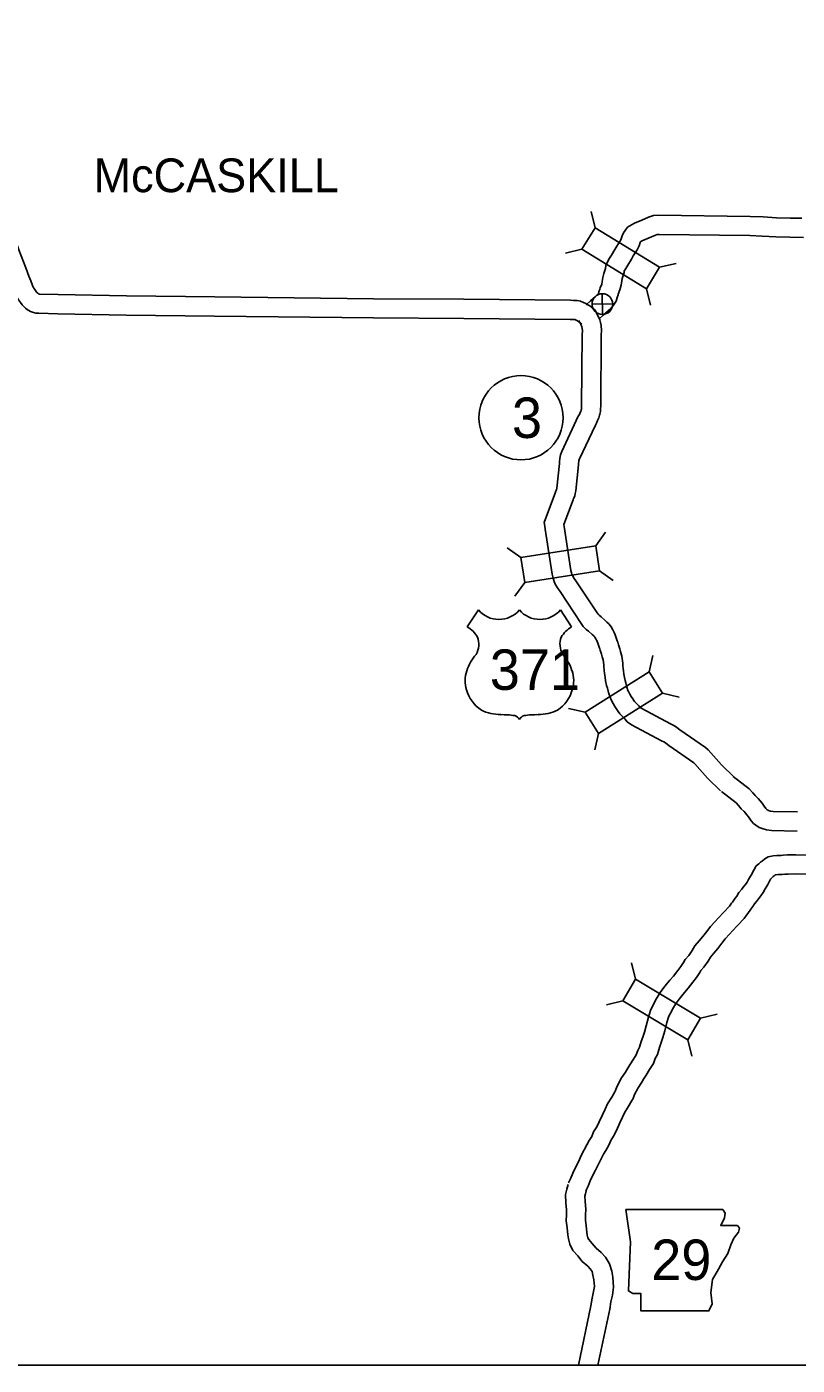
# Model space of a CAD drawing. Extents: x 79818 to 83933, y 50884 to 53307.
# Drawn here: x 81014.4 to 81175.4, y 52610.7 to 52890.4 of the extents above; entities that cross this region are included whole.
import ezdxf

# ---------------------------------------------------------------- set-up
doc = ezdxf.new("R2010")
doc.units = 0
for name, color, linetype in [('Level 10', 7, 'Continuous'), ('Level 15', 7, 'Continuous'), ('Level 20', 7, 'Continuous'), ('Level 21', 7, 'Continuous'), ('Level 22', 7, 'Continuous'), ('Level 26', 7, 'Continuous'), ('Level 27', 7, 'Continuous'), ('Level 6', 7, 'Continuous'), ('R_No Plot', 7, 'Continuous')]:
    doc.layers.add(name, color=color, linetype=linetype)

msp = doc.modelspace()

# ---------------------------------------------------------------- linework, layer by layer
at = {"layer": 'Level 10'}
for points in [[(81131.31, 52832.27), (81132.24, 52833.12), (81133.27, 52833.99), (81133.58, 52834.29), (81133.83, 52834.57), (81133.89, 52834.66), (81133.98, 52835), (81134.18, 52835.56), (81134.24, 52835.8), (81134.56, 52836.59), (81134.69, 52837.12), (81134.82, 52837.97), (81135, 52838.82), (81135.34, 52839.86), (81135.41, 52840.47), (81136.09, 52841.77), (81136.6, 52842.64), (81137.32, 52843.81), (81137.71, 52844.54), (81138.08, 52845.09), (81138.48, 52845.71), (81138.63, 52846.04), (81138.84, 52846.7), (81139.11, 52847.31), (81139.45, 52847.77), (81139.96, 52848.52), (81141.43, 52849.34), (81142.96, 52849.97), (81144.37, 52850.55), (81145.37, 52850.92), (81146.47, 52850.98), (81165.61, 52850.73), (81168.32, 52850.62), (81171.11, 52850.44), (81173.98, 52850.39), (81176.37, 52850.35)], [(81133.95, 52829.27), (81134.88, 52830.12), (81135.93, 52831.01), (81136.47, 52831.51), (81137.06, 52832.19), (81137.59, 52833.04), (81137.8, 52833.8), (81138, 52834.36), (81138.04, 52834.52), (81138.39, 52835.37), (81138.62, 52836.36), (81138.75, 52837.25), (81138.87, 52837.79), (81139.26, 52839), (81139.29, 52839.27), (81139.58, 52839.82), (81140.03, 52840.58), (81140.79, 52841.82), (81141.14, 52842.48), (81141.42, 52842.89), (81141.99, 52843.77), (81142.37, 52844.59), (81142.59, 52845.29), (81142.59, 52845.3), (81142.7, 52845.45), (81142.72, 52845.48), (81143.18, 52845.73), (81144.48, 52846.27), (81145.82, 52846.82), (81146.19, 52846.95), (81146.56, 52846.97), (81165.5, 52846.73), (81168.11, 52846.62), (81170.95, 52846.44), (81173.9, 52846.39), (81176.72, 52846.34)], [(81181.86, 52717.23), (81175.13, 52717.37), (81173.37, 52717.31), (81172.5, 52717.27), (81172.06, 52717.21), (81171.74, 52717.22), (81171.18, 52717.2), (81170.42, 52717.12), (81170.03, 52717.05), (81169.38, 52716.93), (81168.69, 52716.53), (81168.15, 52716.11), (81167.75, 52715.79), (81167.41, 52715.47), (81166.83, 52715.02), (81166.35, 52714.14), (81165.79, 52713.09), (81165.64, 52712.85), (81165.28, 52712.22), (81164.96, 52711.66), (81164.6, 52711.17), (81164.15, 52710.56), (81163.84, 52710.17), (81163.25, 52709.5), (81162.78, 52708.73), (81162.45, 52708.26), (81161.93, 52707.48), (81161.73, 52707.24), (81161.26, 52706.64), (81160.08, 52705.35), (81158.89, 52704.14), (81158.29, 52703.41), (81157.3, 52702.35), (81156.51, 52701.31), (81155.73, 52700.31), (81154.92, 52699.36), (81154.06, 52698.3), (81153.46, 52697.33), (81152.75, 52696.34), (81152, 52695.45), (81151.67, 52694.87), (81151.11, 52694.03), (81150.45, 52693.19), (81149.54, 52692.02), (81148.79, 52691.16), (81148.13, 52690.32), (81147.58, 52689.6), (81146.82, 52688.61), (81146.35, 52687.85), (81145.83, 52686.95), (81145.54, 52686.32), (81145.18, 52685.71), (81144.8, 52684.83), (81144.35, 52683.4), (81143.89, 52681.64), (81143.52, 52680.31), (81143.15, 52679.21), (81142.85, 52678.34), (81142.49, 52677.16), (81142.12, 52676.43), (81141.77, 52675.55), (81141.21, 52674.64), (81140.44, 52673.45), (81139.82, 52672.45), (81139.55, 52671.93), (81138.73, 52670.76), (81137.76, 52668.89), (81137.46, 52668.12), (81137.3, 52667.81), (81136.68, 52666.73), (81135.8, 52665.33), (81135.28, 52664.18), (81134.76, 52663.02), (81134.04, 52661.53), (81133.53, 52660.5), (81132.88, 52659.44), (81132.49, 52658.49), (81131.98, 52657.63), (81131.43, 52656.74), (81130.3, 52654.5), (81129.69, 52653.22), (81128.99, 52651.88), (81128.5, 52650.81), (81128.04, 52649.66), (81127.64, 52648.78)], [(81181.92, 52713.23), (81175.15, 52713.37), (81173.53, 52713.32), (81172.87, 52713.29), (81172.3, 52713.21), (81171.77, 52713.22), (81171.45, 52713.2), (81170.98, 52713.16), (81170.84, 52713.13), (81170.63, 52712.97), (81170.39, 52712.78), (81170.02, 52712.43), (81169.94, 52712.36), (81169.87, 52712.24), (81169.28, 52711.12), (81169.08, 52710.8), (81168.74, 52710.22), (81168.32, 52709.49), (81167.82, 52708.8), (81167.32, 52708.12), (81166.9, 52707.59), (81166.48, 52707.12), (81166.14, 52706.55), (81165.76, 52706), (81165.13, 52705.07), (81164.85, 52704.73), (81164.32, 52704.05), (81162.98, 52702.59), (81161.87, 52701.46), (81161.3, 52700.78), (81160.37, 52699.77), (81159.69, 52698.87), (81158.83, 52697.78), (81157.99, 52696.79), (81157.33, 52695.98), (81156.79, 52695.11), (81155.9, 52693.88), (81155.3, 52693.16), (81155.08, 52692.77), (81154.36, 52691.68), (81153.6, 52690.72), (81152.62, 52689.47), (81151.87, 52688.6), (81151.29, 52687.88), (81150.76, 52687.18), (81150.12, 52686.34), (81149.78, 52685.78), (81149.39, 52685.12), (81149.1, 52684.47), (81148.75, 52683.89), (81148.56, 52683.43), (81148.19, 52682.29), (81147.75, 52680.6), (81147.35, 52679.14), (81146.94, 52677.91), (81146.65, 52677.09), (81146.21, 52675.65), (81145.77, 52674.79), (81145.36, 52673.75), (81144.59, 52672.5), (81143.83, 52671.33), (81143.3, 52670.46), (81142.97, 52669.84), (81142.16, 52668.68), (81141.41, 52667.24), (81141.11, 52666.46), (81140.8, 52665.88), (81140.11, 52664.68), (81139.33, 52663.43), (81138.92, 52662.53), (81138.39, 52661.33), (81137.63, 52659.77), (81137.04, 52658.57), (81136.46, 52657.62), (81136.07, 52656.69), (81135.4, 52655.56), (81134.93, 52654.79), (81133.89, 52652.73), (81133.27, 52651.43), (81132.58, 52650.11), (81132.17, 52649.23), (81131.72, 52648.1), (81131.28, 52647.13)], [(81127.53, 52648.48), (81127.26, 52647.48), (81127.01, 52646.36), (81127.1, 52644.66), (81127.22, 52643.15), (81127.2, 52642.16), (81127.17, 52640.88), (81127.32, 52639.4), (81127.49, 52637.92), (81127.63, 52637.09), (81127.88, 52635.96), (81128.53, 52634.7), (81129.56, 52633.55), (81130.51, 52632.39), (81131.65, 52631.37), (81132.17, 52630.82), (81132.54, 52630.25), (81132.73, 52629.52), (81132.89, 52628.57), (81133.03, 52627.14), (81132.88, 52626.11), (81132.54, 52624.71), (81132.31, 52623.09), (81129.69, 52610.7)], [(81131.39, 52647.43), (81131.15, 52646.53), (81131.04, 52646.02), (81131.09, 52644.91), (81131.22, 52643.28), (81131.2, 52642.08), (81131.18, 52641.03), (81131.3, 52639.82), (81131.45, 52638.5), (81131.56, 52637.86), (81131.68, 52637.32), (81131.85, 52636.98), (81132.6, 52636.15), (81133.41, 52635.16), (81134.44, 52634.23), (81135.33, 52633.3), (81136.23, 52631.9), (81136.65, 52630.37), (81136.86, 52629.09), (81137.05, 52627.04), (81136.81, 52625.35), (81136.48, 52623.97), (81136.26, 52622.4), (81133.78, 52610.7)]]:
    msp.add_lwpolyline(points, dxfattribs=at)
at = {"layer": 'Level 15'}
for points in [[(81008.91, 52854.75), (81012.76, 52843.76), (81014.23, 52839.98), (81014.82, 52838.28), (81015.25, 52837.25), (81015.53, 52836.54), (81015.7, 52836.1), (81015.81, 52835.87), (81015.89, 52835.75), (81016.07, 52835.46), (81016.35, 52835.05), (81016.44, 52834.94), (81016.69, 52834.69), (81016.76, 52834.62), (81016.91, 52834.52), (81017.13, 52834.5), (81020.96, 52834.39), (81035.25, 52834.12), (81053.7, 52833.91)], [(81005.13, 52853.43), (81009.01, 52842.37), (81010.47, 52838.59), (81011.08, 52836.86), (81011.53, 52835.76), (81011.81, 52835.05), (81012.04, 52834.5), (81012.33, 52833.88), (81012.54, 52833.57), (81012.71, 52833.29), (81013.1, 52832.72), (81013.44, 52832.27), (81013.88, 52831.84), (81014.14, 52831.58), (81014.56, 52831.23), (81014.84, 52831.09), (81015.17, 52830.86), (81015.79, 52830.65), (81016.32, 52830.54), (81016.96, 52830.51), (81020.87, 52830.4), (81035.19, 52830.12), (81053.66, 52829.91)], [(81053.7, 52833.91), (81053.71, 52833.91), (81086.89, 52833.53)], [(81086.88, 52833.53), (81105.76, 52833.43), (81128.04, 52833.21), (81128.64, 52833.19), (81129.43, 52833.19), (81130.12, 52833), (81130.76, 52832.78), (81131.22, 52832.51), (81131.55, 52832.35), (81132.08, 52832.05), (81132.43, 52831.75), (81132.54, 52831.66), (81133.21, 52831.14)], [(81053.66, 52829.91), (81086.85, 52829.53)], [(81086.86, 52829.53), (81105.73, 52829.43), (81127.97, 52829.21), (81128.59, 52829.19), (81128.87, 52829.19), (81128.93, 52829.18), (81129.09, 52829.12), (81129.35, 52828.97), (81129.71, 52828.8), (81129.74, 52828.78), (81129.82, 52828.71), (81130.04, 52828.53), (81130.41, 52828.25)], [(81129.82, 52828.97), (81130.36, 52827.84), (81130.4, 52827.67), (81130.49, 52827.3), (81130.53, 52826.86), (81130.48, 52826.07), (81130.37, 52811.17), (81130.35, 52810.82), (81130.34, 52810.5), (81130.34, 52810.49), (81130.28, 52810.29), (81130.2, 52810), (81130.09, 52809.76), (81129.9, 52809.37), (81129.68, 52808.97), (81126.21, 52801.59), (81125.98, 52800.89), (81125.89, 52800.57), (81125.82, 52800.11), (81125.75, 52799.51), (81125.74, 52799.11), (81125.17, 52793.98), (81125.11, 52793.62), (81125, 52793.4), (81124.82, 52792.93), (81122.83, 52787.57), (81122.56, 52786.75), (81122.65, 52785.99), (81122.72, 52785.39), (81124.21, 52775.97), (81124.42, 52775.17), (81124.57, 52774.64), (81124.87, 52773.92), (81125.47, 52772.91), (81125.88, 52772.33), (81130.3, 52765.7), (81130.7, 52765.07), (81131.35, 52764.45), (81131.79, 52764.06), (81132.59, 52763.38), (81132.91, 52763.09), (81133.02, 52762.98), (81133.14, 52762.82), (81133.31, 52762.48), (81133.52, 52762.09)], [(81133.21, 52831.14), (81134.18, 52829.14), (81134.3, 52828.56), (81134.45, 52827.96), (81134.54, 52826.91), (81134.48, 52825.93), (81134.37, 52811.01), (81134.34, 52810.62), (81134.33, 52809.97), (81134.19, 52809.42), (81134.12, 52809.19), (81133.98, 52808.66), (81133.71, 52808.06), (81133.45, 52807.52), (81133.24, 52807.15), (81129.93, 52800.08), (81129.82, 52799.76), (81129.78, 52799.56), (81129.74, 52799.21), (81129.73, 52798.82), (81129.13, 52793.43), (81129.04, 52792.86), (81128.92, 52792.28), (81128.66, 52791.78), (81128.57, 52791.54), (81126.64, 52786.33), (81126.69, 52785.94), (81128.13, 52776.78), (81128.27, 52776.24), (81128.35, 52775.96), (81128.46, 52775.7), (81128.82, 52775.11), (81129.17, 52774.61), (81133.65, 52767.88), (81133.81, 52767.63), (81134.04, 52767.41), (81134.43, 52767.08), (81135.23, 52766.37), (81135.66, 52765.99), (81136.03, 52765.62), (81136.55, 52764.95), (81136.86, 52764.33), (81137.21, 52763.68), (81137.39, 52763.34)], [(81133.55, 52762.11), (81133.8, 52761.34), (81134.12, 52760.53), (81134.19, 52760.38), (81134.25, 52760.14), (81134.5, 52759.27), (81134.67, 52758.74), (81134.84, 52758.06), (81134.99, 52757.05), (81135.01, 52756.61), (81135.05, 52755.92), (81135.13, 52755.2), (81135.27, 52754.46), (81135.37, 52753.71), (81135.59, 52752.75), (81135.76, 52752.2), (81136, 52751.27), (81136.32, 52750.26), (81136.56, 52749.74), (81136.94, 52748.97), (81137.34, 52748.31), (81137.7, 52747.73), (81138.02, 52747.26), (81138.34, 52746.83), (81138.8, 52746.36), (81139.03, 52746.13), (81139.37, 52745.77), (81139.92, 52745.13), (81140.81, 52744.48), (81147.05, 52741.19)], [(81137.36, 52763.33), (81137.56, 52762.69), (81137.8, 52762.09), (81137.95, 52761.76), (81138.1, 52761.24), (81138.34, 52760.41), (81138.52, 52759.81), (81138.76, 52758.85), (81138.98, 52757.41), (81139, 52756.8), (81139.04, 52756.29), (81139.09, 52755.8), (81139.22, 52755.09), (81139.32, 52754.41), (81139.45, 52753.79), (81139.6, 52753.31), (81139.85, 52752.38), (81140.06, 52751.7), (81140.18, 52751.45), (81140.45, 52750.9), (81140.74, 52750.41), (81141.05, 52749.92), (81141.29, 52749.57), (81141.41, 52749.41), (81141.65, 52749.17), (81141.9, 52748.92), (81142.34, 52748.45), (81142.64, 52748.1), (81142.93, 52747.89), (81148.92, 52744.72)], [(81148.92, 52744.72), (81148.95, 52744.71), (81149.75, 52744.27), (81150.25, 52743.93), (81150.9, 52743.46), (81156.25, 52739.75), (81156.84, 52739.25), (81159.6, 52736.14), (81162.22, 52733.58)], [(81147.05, 52741.19), (81147.66, 52740.86), (81147.94, 52740.66), (81148.59, 52740.2), (81153.81, 52736.57), (81154.04, 52736.38), (81156.7, 52733.38), (81159.43, 52730.71)], [(81162.05, 52733.72), (81165.37, 52731.15), (81166.18, 52730.29), (81166.65, 52729.71), (81167.29, 52729.11), (81168.08, 52728.14), (81168.5, 52727.54), (81168.87, 52727.01), (81168.98, 52726.9), (81169.15, 52726.76), (81169.33, 52726.64), (81169.38, 52726.62), (81169.82, 52726.49), (81170.4, 52726.41), (81175.5, 52726.31)], [(81159.6, 52730.57), (81162.67, 52728.18), (81163.18, 52727.64), (81163.73, 52726.97), (81164.35, 52726.38), (81164.89, 52725.72), (81165.22, 52725.25), (81165.78, 52724.43), (81166.32, 52723.91), (81166.76, 52723.55), (81167.47, 52723.06), (81168.11, 52722.82), (81168.99, 52722.56), (81170.09, 52722.42), (81175.42, 52722.31)]]:
    msp.add_lwpolyline(points, dxfattribs=at)
at = {"layer": 'Level 20'}
for p, q in [((81133.17, 52848.37), (81132.34, 52851.79)), ((81130.41, 52843.87), (81126.99, 52843.04)), ((81146.68, 52840.1), (81150.1, 52840.93)), ((81143.92, 52835.6), (81144.75, 52832.18)), ((81133.32, 52781.92), (81135.39, 52784.76)), ((81117.67, 52779.45), (81114.82, 52781.52)), ((81134.14, 52776.7), (81136.99, 52774.63)), ((81118.49, 52774.23), (81116.42, 52771.38)), ((81144.49, 52755.58), (81145.28, 52759.01)), ((81147.3, 52751.1), (81150.73, 52750.32)), ((81131.08, 52747.15), (81127.65, 52747.93)), ((81133.89, 52742.68), (81133.1, 52739.25)), ((81141.66, 52691.36), (81140.81, 52694.78)), ((81138.95, 52686.83), (81135.54, 52685.97)), ((81155.25, 52683.22), (81158.67, 52684.08)), ((81152.54, 52678.69), (81153.4, 52675.28))]:
    msp.add_line(p, q, dxfattribs=at)
for points in [[(81146.68, 52840.1), (81133.17, 52848.37), (81130.41, 52843.87), (81143.92, 52835.6)], [(81133.32, 52781.92), (81117.67, 52779.45), (81118.49, 52774.23), (81134.14, 52776.7)], [(81133.89, 52742.68), (81147.3, 52751.1), (81144.49, 52755.58), (81131.08, 52747.15)], [(81155.25, 52683.22), (81141.66, 52691.36), (81138.95, 52686.83), (81152.54, 52678.69)]]:
    msp.add_lwpolyline(points, close=True, dxfattribs=at)
at = {"layer": 'Level 21'}
msp.add_lwpolyline([(81139.59, 52643.26), (81140.6, 52636.5), (81140.15, 52626.23), (81141.05, 52625.67), (81142.75, 52625.67), (81142.75, 52622.06), (81156.96, 52622.06), (81157.63, 52623.52), (81157.41, 52625.89), (81157.75, 52628.6), (81158.99, 52630.74), (81159.78, 52632.32), (81160.9, 52634.01), (81161.58, 52635.82), (81162.15, 52637.28), (81163.16, 52638.53), (81163.39, 52639.31), (81162.93, 52639.88), (81159.44, 52639.88), (81160.23, 52641.46), (81160.34, 52642.47), (81159.87, 52643.25)], close=True, dxfattribs=at)
at = {"layer": 'Level 22'}
for p, q in [((81108.79, 52768.53), (81106.48, 52764.96)), ((81125.95, 52768.53), (81128.25, 52764.96))]:
    msp.add_line(p, q, dxfattribs=at)
for centre, radius, start, end in [((81113.09, 52772.14), 5.62, 220.075, 319.6701), ((81121.65, 52772.14), 5.62, 220.3299, 319.925), ((81103.46, 52759.78), 6, 30.7809, 59.9883), ((81131.27, 52759.78), 6, 120.0117, 149.2191), ((81104.78, 52761.36), 4.11, 328.8105, 21.2108), ((81129.95, 52761.36), 4.11, 158.7892, 211.1895), ((81115.53, 52752.93), 9.59, 138.9565, 162.6913), ((81119.2, 52752.93), 9.59, 17.3087, 41.0435), ((81112.37, 52753.72), 6.34, 160.9576, 197.3819), ((81122.37, 52753.72), 6.34, 342.6181, 19.0424), ((81113.4, 52753.74), 7.33, 195.1074, 237.1312), ((81121.34, 52753.74), 7.33, 302.8688, 344.8926), ((81113.53, 52756.05), 9.41, 244.0771, 269.5779), ((81113.75, 52729.39), 17.24, 81.1942, 90.9539), ((81115.91, 52744.85), 1.65, 28.0342, 72.9864), ((81118.83, 52744.85), 1.65, 107.0136, 151.9658), ((81120.98, 52729.39), 17.24, 89.0461, 98.8058), ((81121.2, 52756.05), 9.41, 270.4221, 295.9229)]:
    msp.add_arc(centre, radius, start, end, dxfattribs=at)
at = {"layer": 'Level 26'}
for p, q in [((81134.76, 52830.25), (81134.66, 52834.59)), ((81132.54, 52832.37), (81136.88, 52832.47))]:
    msp.add_line(p, q, dxfattribs=at)
msp.add_circle((81134.71, 52832.42), 2.17, dxfattribs=at)
at = {"layer": 'Level 27'}
msp.add_circle((81117.7, 52808.67), 8.8, dxfattribs=at)
at = {"layer": 'R_No Plot'}
msp.add_lwpolyline([(80798.6, 53193.52), (81459.98, 53193.52), (81459.98, 52610.7), (80798.6, 52610.7)], close=True, dxfattribs=at)
msp.add_lwpolyline([(80798.6, 53193.52), (81459.98, 53193.52), (81459.98, 52610.7), (80798.6, 52610.7)], close=True, dxfattribs=at)

# ---------------------------------------------------------------- texts
at = {"layer": 'Level 21'}
msp.add_text('29', height=8.448, dxfattribs=at).set_placement((81144.92, 52628.51))
at = {"layer": 'Level 22'}
msp.add_text('371', height=8.448, dxfattribs=at).set_placement((81111.18, 52751.81))
at = {"layer": 'Level 27'}
msp.add_text('3', height=8.45, dxfattribs=at).set_placement((81115.81, 52804.44))
at = {"layer": 'Level 6'}
msp.add_text('McCASKILL', height=7.04, dxfattribs=at).set_placement((81028.36, 52855.8))

doc.saveas('drawing.dxf')
